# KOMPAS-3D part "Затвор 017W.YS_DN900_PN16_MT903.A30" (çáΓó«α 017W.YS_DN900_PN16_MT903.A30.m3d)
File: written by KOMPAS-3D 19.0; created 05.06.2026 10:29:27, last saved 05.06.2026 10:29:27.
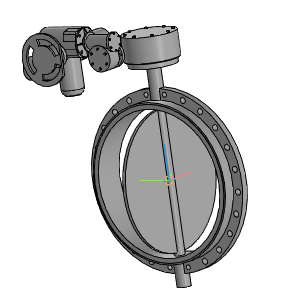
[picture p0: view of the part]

Document properties: Автор: Энергия; Полное имя файла: ..\..\..\3d для проектировщиков\x.x Тип 017W.Y(S) Затвор дисковый поворотный межфланцевый\Затвор 017W.Y(S)_DN32-DN1200_QT.A_MT903.A\Затвор 017W.YS_DN900_PN16_MT903.A30.a3d

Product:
- Part/product: Затвор 017W.YS_DN900_PN16_MT903.A30
    Масса: 731.088

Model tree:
1. Операция без истории:1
